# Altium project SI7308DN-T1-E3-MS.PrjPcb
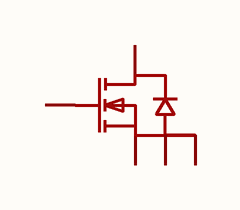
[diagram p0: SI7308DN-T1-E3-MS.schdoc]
1 sheet, 1 parts. Net scope: global (net labels, ports and power ports of the same name join across sheets).

## Sheet SI7308DN-T1-E3-MS.schdoc
size 127 x 101 mm

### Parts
Q?  si7308dn-t1-e3-ms  [PDFN3333-8_L3.1-W3.2-P0.65-LS3.4-BL_1]  (value not drawn)

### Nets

Not connected (* = marked no-connect by the designer): Q? 1(S) 2(S) 3(S) 4(G) 5(D)

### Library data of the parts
Q? = si7308dn-t1-e3-ms: 数量:1个N沟道;漏源电压(Vdss):60V;连续漏极电流(Id):15A;导通电阻(RDS(on)):28mΩ@10V;耗散功率(Pd):34.7W;阈值电压(Vgs(th)):1.6V;; Manufacturer: MSKSEMI(美森科); AddInBom: yes; ModelId: c288237aeb774e1d92142cc9eea176d4; ModelTransform: 118.8974,118.8974,0,90,0,0,0,19.486,0; Number: 1个N沟道; Drain to Source Voltage: 60V; Current - Continuous Drain(Id): 15A; Pd - Power Dissipation: 34.7W; Gate Threshold Voltage (Vgs(th)): 1.6V; Gate Charge(Qg): 20.3nC; Input Capacitance(Ciss): 1.148nF; Reverse Transfer Capacitance (Crss@Vds): 49.4pF; Type: N沟道; Output Capacitance(Coss): 58.5pF; Vgs: ±20V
